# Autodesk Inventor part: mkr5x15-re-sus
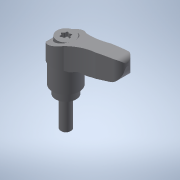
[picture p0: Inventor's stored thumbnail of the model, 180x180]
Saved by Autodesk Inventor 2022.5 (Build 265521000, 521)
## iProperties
Created: 2017-09
Part Number: mkr5x15-re-sus
Material: 一般
Document SubType Name: Modeling
Designer: imaocorp
Density: 1 g/cm^3
Appearance: 既定
Author: imaocorp
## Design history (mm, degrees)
node "mkr5x15-re-sus.x_t1"
node "mkr5x15-re-sus"
node "Base1"
